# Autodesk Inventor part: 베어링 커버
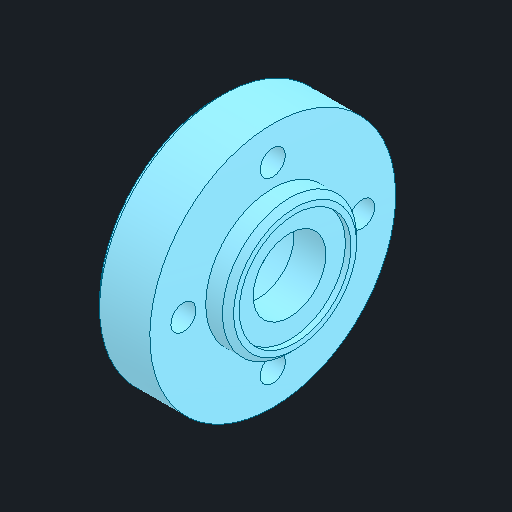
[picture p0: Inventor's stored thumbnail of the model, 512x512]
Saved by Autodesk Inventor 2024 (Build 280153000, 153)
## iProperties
Created: 2024-05
Part Number: 베어링 커버
Material: 강철, 연강
Document SubType Name: Modeling
Designer: kh_501
Density: 7.85 g/cm^3
Appearance: 기본값
Author: jhkim
Sending System: Autodesk Inventor 2025
Preprocessor: ST-DEVELOPER v20
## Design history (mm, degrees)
node "베어링 커버1"
node "솔리드2"
node "솔리드1"
